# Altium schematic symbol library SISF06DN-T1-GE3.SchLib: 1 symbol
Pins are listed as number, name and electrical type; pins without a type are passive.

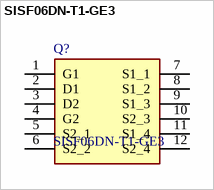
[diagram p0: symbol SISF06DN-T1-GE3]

## SISF06DN-T1-GE3
designator Q?
1-MOSFET Dual N-Ch 30V(S1-S2); Manufacturer_Name: Vishay; Geometry.Height: 0.8mm
footprint SISF06DNT1GE3
pins: 1 G1, 2 D1, 3 D2, 4 G2, 5 S2_1, 6 S2_2, 7 S1_1, 8 S1_2, 9 S1_3, 10 S2_3, 11 S1_4, 12 S2_4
